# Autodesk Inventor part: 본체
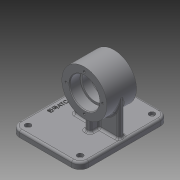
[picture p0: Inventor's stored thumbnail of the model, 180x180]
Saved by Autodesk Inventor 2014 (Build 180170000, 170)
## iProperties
Created: 2019-09
Part Number: 본체
Material: Generic
Document SubType Name: Modeling
Designer: kh
Density: 1 g/cm^3
Appearance: Default
Mass: 205.415 g
Surface Area: 495.884 cm^2
Volume: 205.415 cm^3
Author: kh
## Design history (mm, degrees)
sketch "Sketch1"
  geometry: L1 (-63, -49)-(63, -49); L2 (63, -49)-(63, 49); L3 (63, 49)-(-63, 49); L4 (-63, 49)-(-63, -49); L5 (-63, -49)-(63, 49); L6 (63, -49)-(-63, 49); 1 further point
  constraints: 12 end point, 2 midpoint, 2 parallel, 1 horizontal, 1 perpendicular
  dimensions: "d0" = 126 distance of L2.end L3.end; "d1" = 98 distance of L1.end L2.end
extrude "Extrusion1" new body sketch "Sketch1" distance "d2" = 9; taper "d3" = 0 deg
fillet "Fillet1" dims "d4" = 12
sketch "Sketch2"
  geometry: A1 r 12 centre (-51, 37) between (-51, 49) and (-63, 37) reference; A2 r 12 centre (51, 37) between (63, 37) and (51, 49) reference; A3 r 12 centre (51, -37) between (51, -49) and (63, -37) reference; A4 r 12 centre (-51, -37) between (-63, -37) and (-51, -49) reference; 5 further points
  constraints: 4 coincident
hole "Hole1" sketch "Sketch2" at (-51, 37), (-51, -37), (51, -37), (51, 37) diameter "d5" = 4.5; stored, may be unused: countersink angle "d9" = 90 deg, drill point angle "d11" = 118 deg; dims "d6" = 6, "d7" = 8, "d8" = 4.4, "d10" = 8
workplane "Work Plane1"
sketch "Sketch5"
  geometry: L1 (0, 0)-(102, 0) reference; L2 (72, -59)-(30, -59); L3 (30, -59)-(30, -91); L4 (30, -91)-(72, -91); L5 (72, -91)-(72, -59); L6 (30, -80)-(45, -80); L7 (45, -80)-(45, -77); L8 (45, -77)-(57, -77); L9 (57, -77)-(57, -80); L10 (57, -80)-(72, -80); 3 further points
  constraints: 18 end point, 5 perpendicular, 4 parallel, 2 collinear, 2 midpoint, 2 point on line, 1 vertical alignment
  dimensions: "d14" = 42 distance of L2.start L2.end; "d15" = 59 distance from line of L1 L2.start; "d16" = 64 diameter of L4 L2; "d17" = 42 diameter of L6 L2; "d18" = 36 diameter of L8 L2; "d19" = 15 distance of L6.start L6.end
revolve "Revolution1" sketch "Sketch5" stored, may be unused: angle "d20" = 90 deg
sketch "Sketch6"
  geometry: C1 r 32 at (0, 0) reference; A1 r 26 centre (0, 0) between (-26, 0) and (0, -26); 3 further points
  constraints: 4 point on circle, 2 horizontal alignment, 2 vertical alignment, 1 centre point, 1 coincident
  dimensions: "d22" = 52 diameter of A1
hole "Hole2" sketch "Sketch6" at (-26, 0), (0, -26), (26, 0), (0, 26) diameter "d23" = 3.242; stored, may be unused: countersink angle "d27" = 90 deg, drill point angle "d29" = 118 deg; dims "d24" = 8, "d25" = 8, "d26" = 4.4, "d28" = 10
mirror "Mirror1"
sketch "Sketch9"
  geometry: L1 (21, -19)-(-21, -19) reference; L2 (21, 45)-(-21, 45) reference; L3 (51, 49)-(-51, 49) reference; L4 (-4, 45)-(-4, -19); L5 (4, 45)-(4, -19); L6 (4, -19)-(-4, -19); L7 (-4, 45)-(4, 45); L8 (0, 0)-(0, 18.132)
  constraints: 10 end point, 4 point on line, 3 perpendicular, 2 collinear, 1 other
  dimensions: "d30" = 8 distance of L5.end L4.end
extrude "Extrusion2" join sketch "Sketch9" stored distance "d31" = 6; taper "d32" = 0 deg
sketch "Sketch10"
  geometry: L1 (0, -9)-(102, -9) reference; L2 (51, 0)-(51, -22.25); L3 (34, -9)-(34, -22.25); L4 (68, -9)-(68, -22.25)
  constraints: 6 end point, 2 parallel, 2 point on line, 1 perpendicular, 1 other
  dimensions: "d34" = 34 distance of L4.start L3.start
feature "Rib1" dims "d35" = 1, "d36" = 8, "d37" = 0, "d38" = 0, "d39" = 1, "d40" = 1
feature "Rib2" dims "d41" = 1, "d42" = 8, "d43" = 0, "d44" = 0, "d45" = 1, "d46" = 1
fillet "Fillet2" dims "d47" = 0.3
chamfer "Chamfer1" distance "d48" = 1; stored, may be unused: second distance "d49" = 2, angle "d50" = 45 deg
fillet "Fillet3" dims "d51" = 3
fillet "Fillet4" dims "d52" = 3
sketch "Sketch11"
  geometry: L1 (-63, 37)-(-63, -37) reference; L2 (-51, -49)-(51, -49) reference; L3 (20.739, -42.002)-(-20.739, -42.002); L4 (-20.739, -42.002)-(-20.739, -35.998); L5 (-20.739, -35.998)-(20.739, -35.998); L6 (20.739, -35.998)-(20.739, -42.002); L7 (-20.739, -35.998)-(20.739, -42.002); L8 (20.739, -35.998)-(-20.739, -42.002); 2 further points
  constraints: 4 end point, 1 midpoint, 2 other
  dimensions: "d53" = 63 distance from line of L1 point (0, -39); "d54" = 10 distance from line of L2 point (0, -39)
emboss "Emboss1" sketch "Sketch11" dims "d55" = 0.5, "d56" = 0
body "Solid1"
other parameters: "d13" = -36
